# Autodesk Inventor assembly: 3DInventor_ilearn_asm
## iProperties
Created: 2006-11
Part Number: 3DInventor_ilearn_asm
Document SubType Name: Assembly
Designer: conardl1
Translation Standard: STEP AP203
File Name: ILEARN_ASM
Preprocessor: PRO/ENGINEER BY PARAMETRIC TECHNOLOGY CORPORATION, 2004280
Postprocessor: Build: 211m, Release: 10 - Date: Fri 03/18/2005
Sent Units: MILLIMETERS
Uncertainty: 0.01234991083547
DESCRIPTION: iLearn Assembly
MODELED_BY: L Conard
Author: conardl1
